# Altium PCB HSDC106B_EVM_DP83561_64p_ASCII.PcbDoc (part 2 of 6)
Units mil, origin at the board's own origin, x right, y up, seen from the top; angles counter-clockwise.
Board outline 8750.24 x 6394.7 mil, 6 copper layers (Top Layer, GND, SIG1, SIG2, GND1, Bottom Layer), stack 60.4 mil thick; 475 components, 330 nets, 1628 pads, 1086 vias.
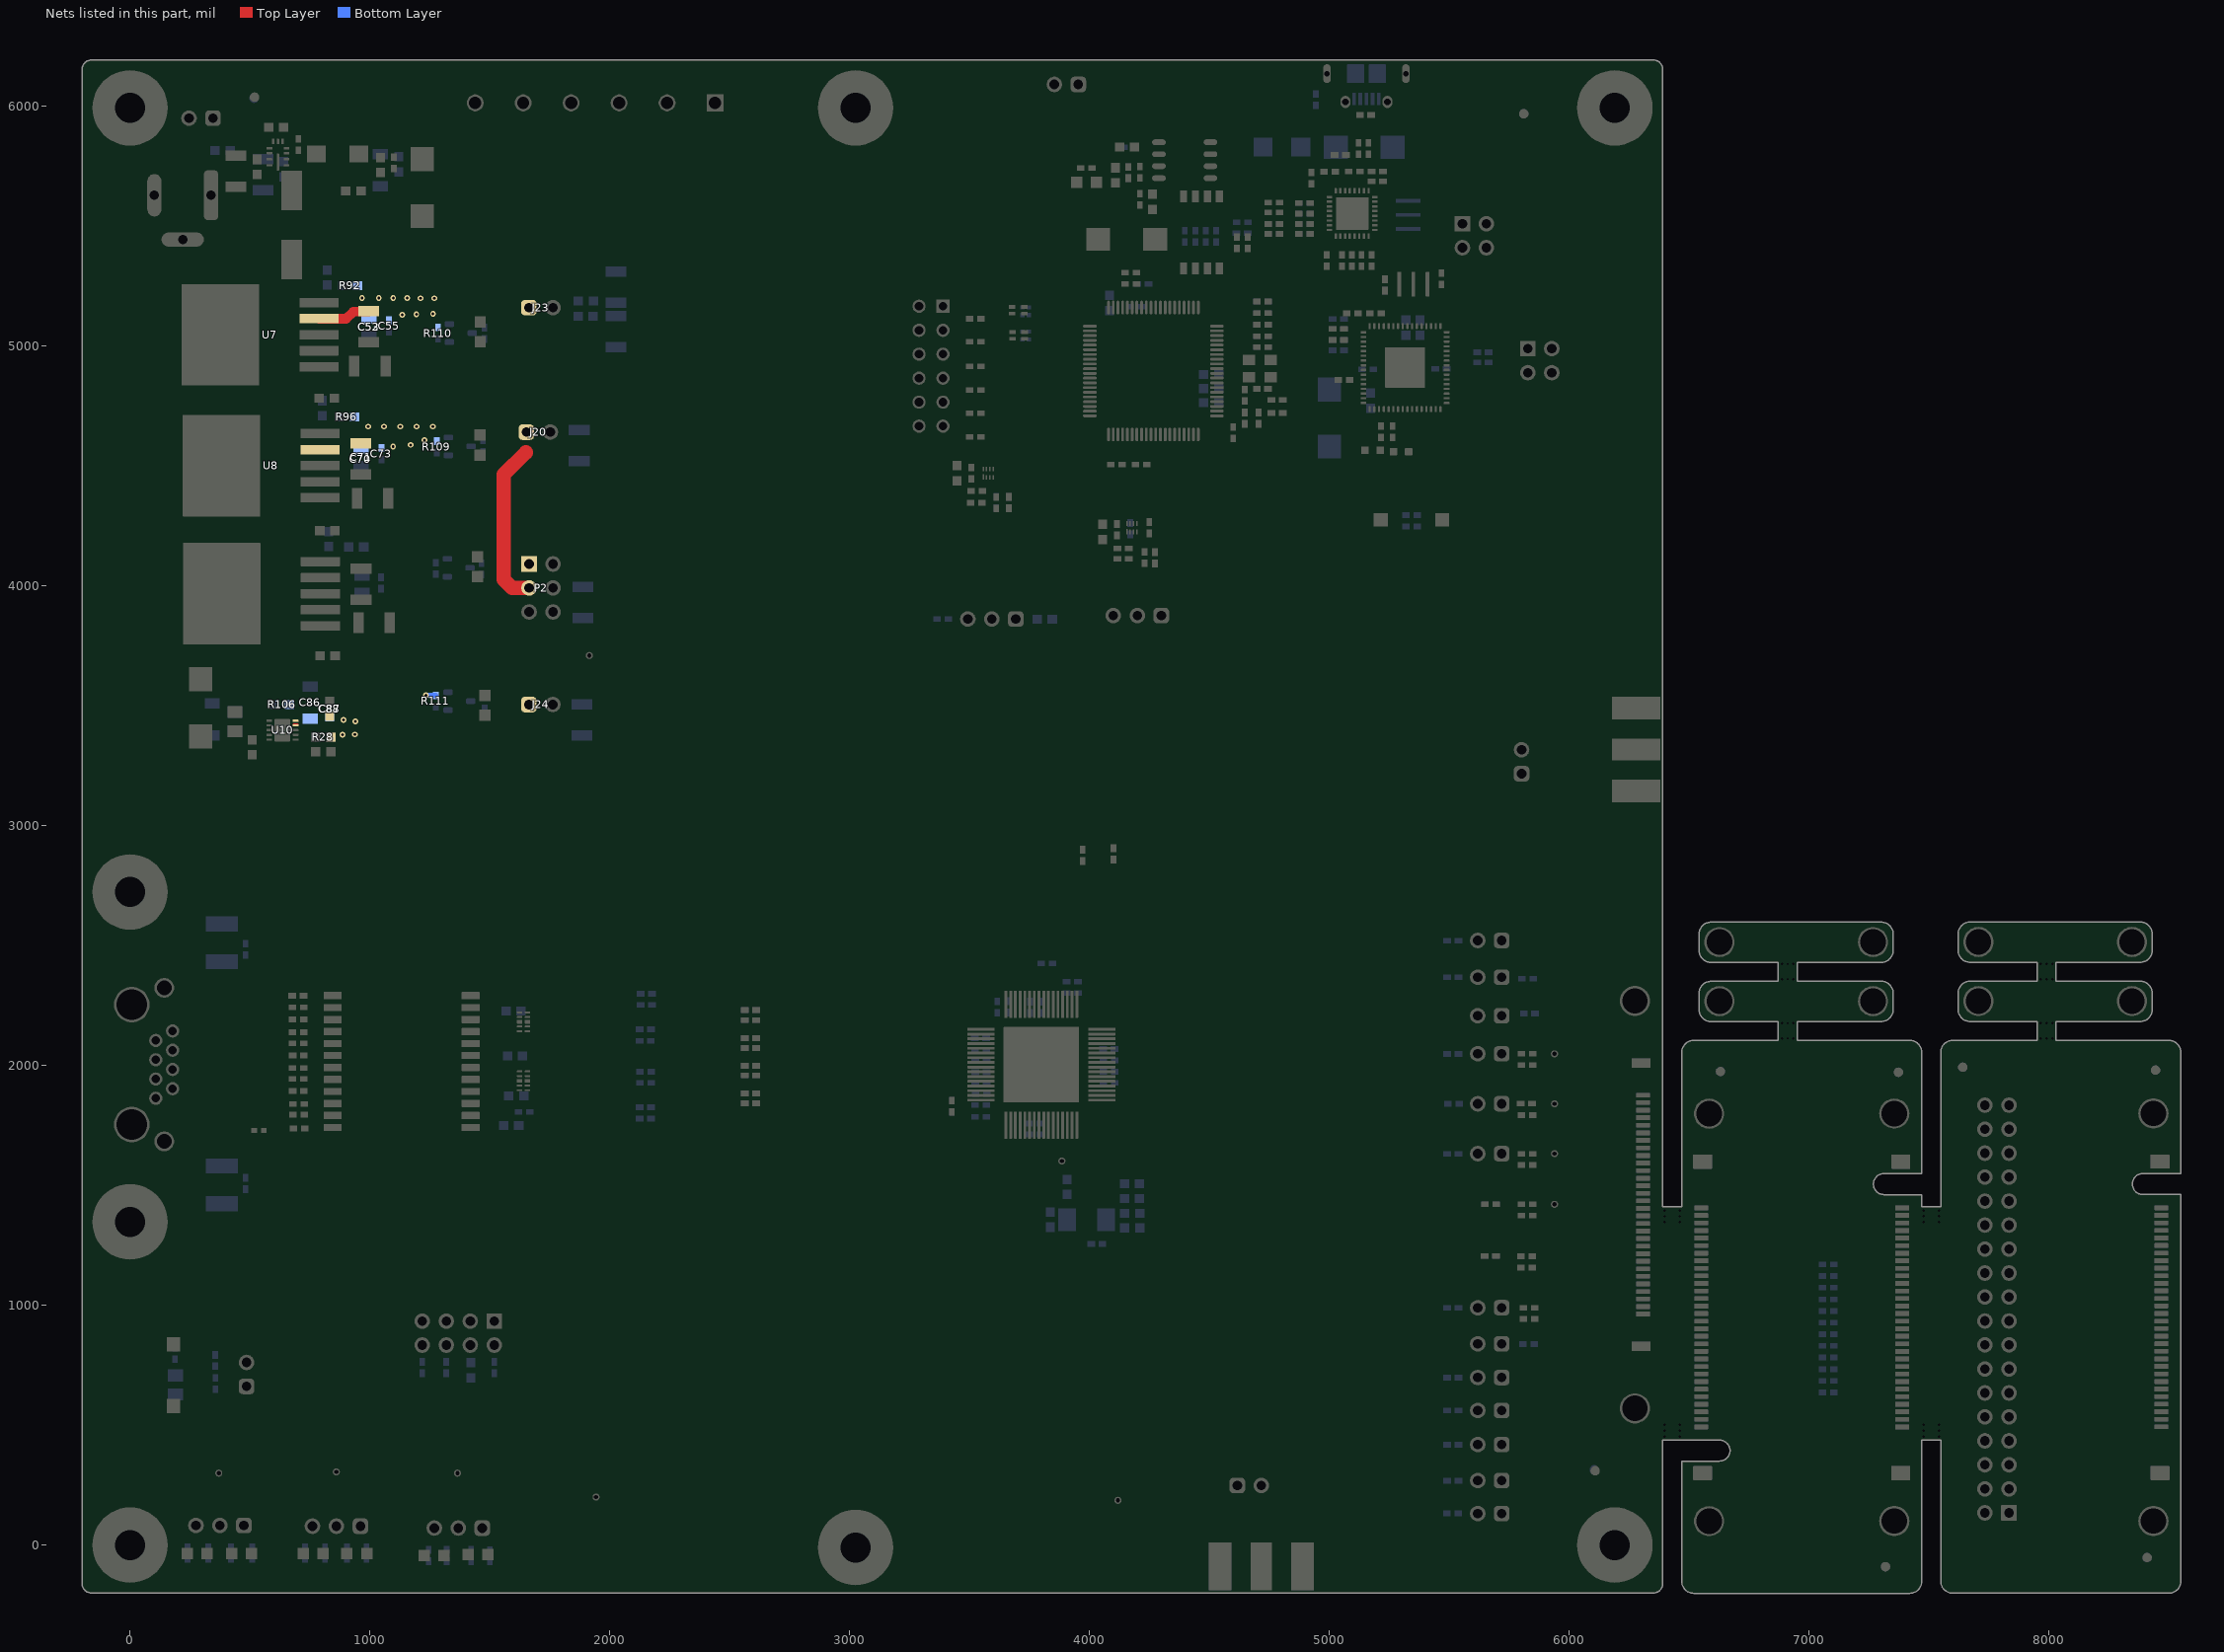
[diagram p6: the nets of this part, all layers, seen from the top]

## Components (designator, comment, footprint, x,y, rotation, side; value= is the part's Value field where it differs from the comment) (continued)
H4 "1902C" Keystone_1902C 0,5993.7 r180 bottom
H5 "1902C" Keystone_1902C 3025,5993.7 r180 bottom
H6 "1902C" Keystone_1902C 0,2723.83 r180 bottom
H7 "1902C" Keystone_1902C 6190.55,5993.7 r180 bottom
H8 "1902C" Keystone_1902C 6190.55,0 r180 bottom
J1 "ERF8-030-01-L-D-EM2-TR" Samtec_ERF8-030-01-x-D-EM2 8550.21,950 r270 top locked
J2 "TSW-118-07-G-D" TSW-118-07-G-D 7783.6,984.61 r90 top
J3 "TSW-102-07-G-D" TSW-102-07-G-D 5605,5460.7 r270 top
J4 "ERM8-030-01-L-D-EM2-TR" Samtec_ERM8-030-01-L-D-EM2 6390.55,1420 r180 top
J5 "TSW-102-07-G-S" TSW-102-07-G-S 5668.99,839.65 r180 top
J6 "TSW-102-07-G-S" TSW-102-07-G-S 5668.6,2207.61 r180 top
J8 "802-10-012-10-001000" Mill-Max_802-10-012-10-001000 3339.6,4916.61 r270 top
J9 "TSW-102-07-G-D" TSW-102-07-G-D 5877.6,4939.61 r270 top
J10 "TSW-102-07-G-S" TSW-102-07-G-S 485.95,711.76 r90 top
J11 "142-0701-851" Emerson_142-0701-851 4716.6,-199.39 r180 top
J12 "TSW-102-07-G-S" TSW-102-07-G-S 4666.6,248.61 r0 top
J13 "142-0701-851" Emerson_142-0701-851 6389.6,3318.11 r270 top
J14 "TSW-102-07-G-S" TSW-102-07-G-S 5801.67,3266.74 r90 top
J15 "CMP-0075407-2" TSW-103-07-G-S 3592.83,3862 r180 top
J16 "PJ-002AH" CUI_PJ-002AH 219.6,5629.61 r180 top
J17 "1729160" Phoenix_1729160 1939,6014.7 r180 top
J18 "TSW-102-07-G-S" TSW-102-07-G-S 295.6,5950.61 r180 top
J19 "ERF8-030-01-L-D-EM2-TR" Samtec_ERF8-030-01-x-D-EM2 7469.7,949.61 r270 top locked
J20 "TSW-102-07-G-S" TSW-102-07-G-S 1702,4641.61 r0 top
J21 "CMP-0075405-2" TSW-102-07-G-S 3903.6,6091.61 r180 top
J22 "ERF8-030-01-L-D-EM2-TR" Samtec_ERF8-030-01-x-D-EM2 6469.58,949.61 r90 top locked
J23 "CMP-0075405-2" TSW-102-07-G-S 1713,5160.7 r0 top
J24 "CMP-0075405-2" TSW-102-07-G-S 1712.6,3505.61 r0 top
J27 "1-406541-1" TEC_1-406541-1 114.53,2003.48 r270 top
J28 "CMP-0075407-2" TSW-103-07-G-S 1368.5,70.98 r180 top
J29 "CMP-0075405-2" TSW-102-07-G-S 5668.99,1632.34 r180 top locked
J30 "CMP-0075405-2" TSW-102-07-G-S 5668.99,1840.58 r180 top locked
J31 "CMP-0075405-2" TSW-102-07-G-S 5668.99,2048.82 r180 top
J32 "CMP-0075405-2" TSW-102-07-G-S 5668.99,990 r180 top locked
J33 "CMP-0075407-2" TSW-103-07-G-S 860.5,78.98 r180 top
J34 "CMP-0075405-2" TSW-102-07-G-S 5668.99,561.57 r180 top
J35 "CMP-0075405-2" TSW-102-07-G-S 5668.99,131.67 r180 top
J36 "CMP-0075405-2" TSW-102-07-G-S 5668.99,269.01 r180 top
J37 "CMP-0075405-2" TSW-102-07-G-S 5668.99,419.03 r180 top
J38 "CMP-0075407-2" TSW-103-07-G-S 374.5,81.98 r180 top
J39 "CMP-0075405-2" TSW-102-07-G-S 5668.99,698.77 r180 top
J40 "CMP-0075405-2" TSW-102-07-G-S 5668.99,2521.41 r180 top
J41 "CMP-0075405-2" TSW-102-07-G-S 5668.99,2368.28 r180 top
J42 "475890001" Molex_0475890001 5154.83,6193.7 r0 bottom
J43 "CMP-0075407-2" TSW-103-07-G-S 4199.6,3876.61 r180 top
L1 "SRP5030T-100M" SRP5030T 865.18,5801.61 r0 top
LD1 "CMP-0002917-2" QTLP630C_Green 1268,-44 r180 top
LD2 "CMP-0002917-2" QTLP630C_Green 1450,-40 r0 top
LD3 "CMP-0002917-2" QTLP630C_Green 763.89,-34.95 r180 top
LD4 "CMP-0002917-2" QTLP630C_Green 945.5,-35 r0 top
LD5 "CMP-0002917-2" QTLP630C_Green 280,-35 r180 top
LD6 "CMP-0002917-2" QTLP630C_Green 465,-35 r180 top
LD7 "QTLP630C4TR" QTLP630C_Green 3987.6,5682.7 r0 top
Logo1 "CE Mark" CE_Mark_5mm 587,1072 r0 top
Logo2 "Texas Instruments" TI_Stacked_Overlay_Small 5699,3956 r0 top
Logo3 "FCC disclaimer" FCC_disclaimer 12309,361.7 r90 top
Logo4 "WEEE logo" WEEE_Minimum 5913,4412 r0 top
M1 "NY PMS 440 0025 PH" "NY PMS 440 0025 PH" 6190.55,5993.7 r0 top locked
M2 "NY PMS 440 0025 PH" "NY PMS 440 0025 PH" 6190.55,0 r0 top locked
M3 "NY PMS 440 0025 PH" "NY PMS 440 0025 PH" 0,5993.7 r0 top locked
M4 "NY PMS 440 0025 PH" "NY PMS 440 0025 PH" 0,0 r0 top locked
M5 "NY PMS 440 0025 PH" "NY PMS 440 0025 PH" 3025,5993.7 r0 top locked
M6 "NY PMS 440 0025 PH" "NY PMS 440 0025 PH" 3025,-10 r0 top locked
M7 "NY PMS 440 0025 PH" "NY PMS 440 0025 PH" 0,2723.83 r0 top locked
M8 "NY PMS 440 0025 PH" "NY PMS 440 0025 PH" 0,1348.16 r0 top locked
P1 "CMP-0075408-3" TSW-104-07-G-D 1368.49,884.31 r180 top
P2 "TSW-103-07-G-D" TSW-103-07-G-D 1713.83,3991.7 r270 top
Q1 "DNBT8105-7" SOT-23 1370,4075.7 r0 bottom
Q2 "DNBT8105-7" SOT-23 1374.4,4582.1 r0 bottom
Q3 "DNBT8105-7" SOT-23 1379,5054.7 r0 bottom
Q4 "DNBT8105-7" SOT-23 1373,3519.7 r0 bottom
R1 "CRCW0402470RJNED" 0402#1 5216,4643.08 r90 top
R2 "CRCW0402470RJNED" 0402#1 5264,4643.08 r90 top
R3 "CRCW0402240KJNED" 0402#1 5037.6,5072.61 r180 top
R4 "CRCW0402220KJNED" 0402#1 5037.6,5025.7 r180 bottom
R5 "CRCW0402150KJNED" 0402#1 5037.6,5072.61 r0 bottom
R6 "CRCW0402220KJNED" 0402#1 5037.6,4982.7 r0 bottom
R7 "RC0402JR-070RL" 0402#1 5232.1,5255.55 r90 bottom
R8 "CRCW040247K0JNED" 0402#1 5096,5136.7 r180 top
R9 "RC0402JR-070RL" 0402#1 5640.6,4974.7 r0 bottom
R10 "RC0402JR-070RL" 0402#1 5640.6,4932.61 r0 bottom
R11 "ERJ-2GE0R00X" 0402#1 3971.39,2876.53 r90 top
R12 "ERJ-2GE0R00X" 0402#1 4100.51,2882.61 r90 top
R13 "ERJ-2GE0R00X" 0402#1 5830.98,838.61 r0 bottom
R14 "ERJ-2GE0R00X" 0402#1 5821.6,1841.61 r0 top
R15 "ERJ-2GE0R00X" 0402#1 5824.6,1631.61 r0 top
R16 "ERJ-2GE0R00X" 0402#1 5824.97,1421.22 r0 top
R17 "ERJ-2GE0R00X" 0402#1 5822.6,1204.24 r0 top
R18 "ERJ-2GE0R00X" 0402#1 5832.24,990 r0 top
R19 "ERJ-2GE0R00X" 0402#1 5824.97,2048.82 r0 top
R20 "ERJ-2GE0R00X" 0402#1 5832.24,942.76 r0 top
R21 "CMP-0025885-5" 0603 819.6,4783.61 r0 top
R22 "CMP-0025885-5" 0603 822.6,4230.61 r0 top
R23 "ERJ-2GE0R00X" 0402#1 5824.97,1793.33 r0 top
R24 "CMP-0025885-5" 0603 823.6,3708.61 r0 top
R25 "ERJ-2GE0R00X" 0402#1 5824.97,1585.09 r0 top
R26 "CMP-0025885-5" 0603 508.6,3327.1 r90 top
R27 "ERJ-2GE0R00X" 0402#1 5824.97,1373.98 r0 top
R28 "RC0603FR-071K87L" 0603 805.6,3370.15 r0 top
R29 "ERJ-2GE0R00X" 0402#1 5822.6,1157 r0 top
R30 "CRCW06034K99FKEAC" 0603 805.6,3370.15 r180 bottom
R31 "ERJ-2GE0R00X" 0402#1 5824.97,2001.57 r0 top
R32 "ERJ-2GE0R00X" 0402#1 5834.22,2216.48 r0 bottom
R33 "ERJ-2GE0R00X" 0402#1 5826.6,2361.61 r0 bottom
R34 "ERJ-2GE0R00X" 0402#1 3822,2426.17 r0 bottom
R35 "CRCW0402374KFKED" 0402#1 3530.65,4396.32 r0 top
R36 "ERJ-2RKF1004X" 0402#1 3527.6,4346.61 r180 top
R37 "CRCW0402374KFKED" 0402#1 4140.6,4156.61 r0 top
R38 "ERJ-2RKF1004X" 0402#1 4140.6,4113.61 r180 top
R39 "ERJ-2GE0R00X" 0402#1 3524.6,5114.61 r0 top
R40 "CRCW0603200KJNEA" 0603 3448.6,4470.61 r270 top
R41 "CRCW0603200KJNEA" 0603 4055.6,4225.61 r270 top
R42 "ERJ-2GE0R00X" 0402#1 3524.6,5018.61 r0 top
R43 "ERJ-2GE0R00X" 0402#1 3524.6,4915.61 r0 top
R44 "ERJ-2GE0R00X" 0402#1 3524.6,4816.61 r0 top
R45 "ERJ-2GE0R00X" 0402#1 3524.6,4720.61 r0 top
R46 "ERJ-2GE0R00X" 0402#1 3524.6,4621.61 r0 top
R47 "CRCW04022K20FKED" 0402#1 3611.45,4346.8 r270 top
R48 "CRCW04022K20FKED" 0402#1 4230.1,4118.11 r270 top
R49 "CRCW040210K0JNED" 0402#1 4721.6,5041.8 r0 top
R50 "CRCW040210K0JNED" 0402#1 4721.6,5090.07 r0 top
R51 "CRCW04022K20FKED" 0402#1 3663.64,4347.8 r270 top
R52 "CRCW040210K0JNED" 0402#1 4721.6,5138.34 r0 top
R53 "CRCW040210K0JNED" 0402#1 4721.6,5186.61 r0 top
R54 "ERJ-2GE0R00X" 0402#1 4169.71,4238.67 r90 bottom
R55 "ERJ-2GE0R00X" 0402#1 3611.45,4348.76 r90 bottom
R56 "ERJ-2GE0R00X" 0402#1 4249.6,4242.98 r90 top
R57 "ERJ-2GE0R00X" 0402#1 3663.64,4347.8 r90 bottom
R58 "CRCW040210K0JNED" 0402#1 4721.6,5041.8 r180 bottom
R59 "CRCW040210K0JNED" 0402#1 4721.6,5090.07 r180 bottom
R60 "CRCW040210K0JNED" 0402#1 4721.6,5138.34 r180 bottom
R61 "CRCW040210K0JNED" 0402#1 4721.6,5186.61 r180 bottom
R62 "CRCW04022K20FKED" 0402#1 4397.6,5458.61 r90 bottom
R63 "CRCW04022K20FKED" 0402#1 4441.6,5458.61 r90 bottom
R64 "CRCW04022K20FKED" 0402#1 4484.6,5458.61 r90 bottom
R65 "CRCW04022K20FKED" 0402#1 4528.6,5458.61 r90 bottom
R66 "CRCW04022K20FKED" 0402#1 4112.22,4506.61 r180 top
R67 "CRCW04022K20FKED" 0402#1 4214.98,4506.61 r0 top
R68 "CRCW04020000Z0ED" 0402#1 4721.6,4995.61 r180 top
R69 "RC0201JR-07470RL" 0201 3734.05,5161.57 r0 bottom
R70 "RC0201JR-07470RL" 0201 3734.05,5129.86 r0 bottom
R71 "RC0201JR-07470RL" 0201 3734.1,5060.61 r0 bottom
R72 "RC0201JR-07470RL" 0201 3734.1,5027.14 r0 bottom
R73 "CRCW04021K40FKED" 0402#1 4648,4699.7 r90 top
R74 "CRCW04021M00FKED" 0402#1 4599.6,4639.61 r270 top
R75 "CRCW040247K0JNED" 0402#1 5343,4295.61 r180 bottom
R76 "CRCW04020000Z0ED" 0402#1 4192.85,5164.73 r0 bottom
R77 "CMP-0025885-5" 0603 3906.6,1493.61 r90 bottom
R78 "CMP-0025885-5" 0603 4178.47,1383.8 r180 bottom
R79 "CRCW0402470RJNED" 0402#1 355.45,674.23 r90 bottom
R80 "ERJ-2GEJ101X" 0402#1 187.29,798.8 r90 bottom
R81 "CMP-0026727-1" 0402#1 4030.97,1255.8 r0 bottom
R82 "CMP-0025885-5" 0603 4177.6,1444.98 r180 bottom
R83 "RMCF0402FT10K0" 0402#1 3426.41,1829.61 r270 bottom
R84 "CMP-0025885-5" 0603 4177.6,1506.61 r180 bottom
R85 "CMP-0026890-5" 0402#1 4273.1,4117.61 r90 top
R86 "CMP-0026890-5" 0402#1 1518.49,740.69 r90 bottom
R87 "CMP-0026890-5" 0402#1 3388.6,3862 r180 bottom
R88 "CMP-0026890-5" 0402#1 1318.49,740.69 r90 bottom
R89 "CMP-0026890-5" 0402#1 1218.49,740.69 r90 bottom
R90 "CMP-0023246-5" 0603 3813.6,3861.61 r180 bottom
R91 "CMP-0022558-4" 0603 1420.6,729.61 r90 bottom
R92 "RC0603FR-071K2L" 0603 918,5252.7 r0 bottom
R93 "CRCW0603100KFKEA" 0603 931.6,5646.61 r0 top
R94 "CMP-0023374-3" 0603 822,5286.2 r270 bottom
R95 "CRCW060324K9FKEA" 0603 931.6,5646.61 r180 bottom
R96 "RC0603FR-072K55L" 0603 904,4705.7 r0 bottom
R97 "CMP-0025885-5" 0603 1899.6,5124.61 r0 bottom
R98 "CMP-0023374-3" 0603 801,4741.2 r270 bottom
R99 "CMP-0025885-5" 0603 1900,5188.7 r0 bottom
R100 "CMP-0022451-4" 0603 943,4162.7 r0 bottom
R101 "CMP-0023374-3" 0603 829,4195.7 r270 bottom
R102 "CMP-0026934-3" 0402#1 1465.6,4071.61 r90 bottom
R103 "CMP-0026934-3" 0402#1 1471.6,4583.61 r90 bottom
R104 "CMP-0026934-3" 0402#1 1477.6,5053.61 r90 bottom
R105 "CMP-0026934-3" 0402#1 1478.6,3513.61 r90 bottom
R106 "CMP-0022746-5" 0603 634,3505.7 r180 bottom
R107 "CMP-0026544-2" 0402#1 704.6,1737.61 r0 top
R108 "CRCW04022K49FKED" 0402#1 1274.6,4072.61 r270 bottom
R109 "CRCW04022K49FKED" 0402#1 1278.6,4580.61 r270 bottom
R110 "CRCW04022K49FKED" 0402#1 1283.6,5054.61 r270 bottom
R111 "CRCW04022K49FKED" 0402#1 1274.6,3519.61 r270 bottom
R112 "ERJ-2GE0R00X" 0402#1 703,1795 r0 top
R113 "ERJ-2GE0R00X" 0402#1 703,1839 r0 top
R114 "CMP-0026544-2" 0402#1 701.38,1893.61 r0 top
R115 "ERJ-2GE0R00X" 0402#1 701,1944 r0 top
R116 "ERJ-2GE0R00X" 0402#1 701,1990 r0 top
R117 "CMP-0026544-2" 0402#1 701.38,2041.7 r0 top
R118 "ERJ-2GE0R00X" 0402#1 701,2092 r0 top
R119 "ERJ-2GE0R00X" 0402#1 2586.65,2231.7 r0 top
R120 "ERJ-2GE0R00X" 0402#1 2586.65,2231.7 r0 bottom
R121 "ERJ-2GE0R00X" 0402#1 700.81,2138.61 r0 top
R122 "ERJ-2GE0R00X" 0402#1 2586.65,2189.7 r0 top
R123 "CMP-0026544-2" 0402#1 700,2192.09 r0 top
R124 "ERJ-2GE0R00X" 0402#1 2586.65,2189.7 r0 bottom
R125 "ERJ-2GE0R00X" 0402#1 700,2243 r0 top
R126 "ERJ-2GE0R00X" 0402#1 1643,1806 r180 bottom
R127 "ERJ-2GE0R00X" 0402#1 2586.65,2114.51 r0 top
R128 "ERJ-2GE0R00X" 0402#1 699.6,2290.61 r0 top
R129 "ERJ-2GE0R00X" 0402#1 2586.65,2114.51 r0 bottom
R130 "ERJ-2GE0R00X" 0402#1 7080.6,636.61 r0 bottom
R131 "ERJ-2GE0R00X" 0402#1 2586.65,2072.7 r0 top
R132 "ERJ-2GE0R00X" 0402#1 7080.6,685.15 r0 bottom
R133 "ERJ-2GE0R00X" 0402#1 2586.65,2072.7 r0 bottom
R134 "ERJ-2GE0R00X" 0402#1 7080.6,733.7 r0 bottom
R135 "ERJ-2GE0R00X" 0402#1 7080.6,782.24 r0 bottom
R136 "ERJ-2GE0R00X" 0402#1 7080.6,830.79 r0 bottom
R137 "ERJ-2GE0R00X" 0402#1 2586.65,1998.51 r0 top
R138 "ERJ-2GE0R00X" 0402#1 2586.65,1998.51 r0 bottom
R139 "ERJ-2GE0R00X" 0402#1 2586.65,1958.51 r0 top
R140 "ERJ-2GE0R00X" 0402#1 2586.65,1958.51 r0 bottom
R141 "ERJ-2GE0R00X" 0402#1 2586.65,1883.51 r0 top
R142 "ERJ-2GE0R00X" 0402#1 2586.65,1883.51 r0 bottom
R143 "ERJ-2GE0R00X" 0402#1 2586.65,1842.51 r0 top
R144 "ERJ-2GE0R00X" 0402#1 2586.65,1842.51 r0 bottom
R145 "CMP-0026727-1" 0402#1 482,1508 r270 bottom
R146 "CMP-0026727-1" 0402#1 482,2484 r90 bottom
R147 "CRCW0402470RJNED" 0402#1 1320.5,-43.4 r90 bottom
R148 "CRCW04022K49FKED" 0402#1 1244.5,-43.4 r270 bottom
R149 "CRCW0402470RJNED" 0402#1 1421.5,-43.4 r90 bottom
R150 "CRCW04022K49FKED" 0402#1 1500,-45 r90 bottom
R151 "CRCW04022K49FKED" 0402#1 5514.94,1631.93 r180 bottom
R152 "CRCW04026K04FKED" 0402#1 5671.47,1205.42 r180 top
R153 "CRCW04022K49FKED" 0402#1 5518.64,1840.17 r180 bottom
R154 "CRCW04022K49FKED" 0402#1 5671.47,1205.42 r0 bottom
R155 "CRCW04026K04FKED" 0402#1 5672.01,1421.22 r180 top
R156 "CRCW04022K49FKED" 0402#1 5514.94,2048.41 r180 bottom
R157 "CRCW0402470RJNED" 0402#1 812.5,-33.4 r90 bottom
R158 "CRCW04022K49FKED" 0402#1 5672.01,1421.22 r0 bottom
R159 "CRCW04022K49FKED" 0402#1 729.5,-33.4 r270 bottom
R160 "CRCW04022K49FKED" 0402#1 5514.94,989.59 r180 bottom
R161 "CRCW0402470RJNED" 0402#1 904,-33.4 r90 bottom
R162 "CRCW04022K49FKED" 0402#1 986,-33.4 r90 bottom
R163 "CRCW04022K49FKED" 0402#1 5514.94,561.16 r180 bottom
R164 "CRCW04022K49FKED" 0402#1 5513.6,132.61 r180 bottom
R165 "CRCW04022K49FKED" 0402#1 5514.94,268.61 r180 bottom
R166 "CRCW0402470RJNED" 0402#1 326.49,-33.43 r90 bottom
R167 "CRCW04022K49FKED" 0402#1 5514.94,418.62 r180 bottom
R168 "CRCW04022K49FKED" 0402#1 239.5,-33.4 r270 bottom
R169 "CRCW04022K49FKED" 0402#1 5514.94,698.36 r180 bottom
R170 "CRCW0402470RJNED" 0402#1 509.5,-33.4 r90 bottom
R171 "CRCW04022K49FKED" 0402#1 420.5,-33.4 r90 bottom
R172 "CRCW04022K49FKED" 0402#1 5514.94,2521 r180 bottom
R173 "CRCW04022K49FKED" 0402#1 5514.94,2367.87 r180 bottom
R174 "CRCW0402100KDHEDP" 0402#1 4210,5725.04 r90 top
R175 "CRCW0402470RJNED" 0402#1 3987.6,5742.61 r0 top
R176 "CRCW0402165KFKED" 0402#1 4210,5612.94 r90 top
R177 "CRCW040233R0JNED" 0402#1 4944,6027.7 r270 bottom
R178 "CRCW04021K50FKED" 0402#1 5200,5729 r0 top
R179 "CRCW040210K0JNED" 0402#1 4989,5357.7 r270 top
R180 "CRCW040227R0JNED" 0402#1 4648,4795.7 r90 top
R181 "CRCW040222R0JNED" 0402#1 5122,5825 r270 top
R182 "CRCW040222R0JNED" 0402#1 5163.41,5824.5 r270 top
R183 "CRCW040227R0JNED" 0402#1 4705,4699.7 r270 top
R184 "CRCW040222R0JNED" 0402#1 4895.98,5596.61 r0 top
R185 "CRCW040222R0JNED" 0402#1 4896.6,5552.61 r0 top
R186 "CRCW040215K0FKED" 0402#1 4769,5557.5 r0 top
R187 "CRCW040215K0FKED" 0402#1 4769,5598.72 r0 top
R188 "CRCW040215K0FKED" 0402#1 5053.44,5357.32 r90 top
R189 "CRCW040215K0FKED" 0402#1 5094.25,5357.61 r90 top
R190 "CRCW040215K0FKED" 0402#1 5134.6,5357.61 r90 top
R191 "CRCW040215K0FKED" 0402#1 5176.79,5357.61 r90 top
R192 "CRCW040222R0JNED" 0402#1 4896.41,5509.5 r0 top
R193 "CRCW040222R0JNED" 0402#1 4896.41,5468.5 r0 top
R194 "CRCW040215K0FKED" 0402#1 4769,5468.5 r0 bottom
R195 "CRCW040215K0FKED" 0402#1 4769,5509.5 r0 bottom
R196 "CRCW040227R0JNED" 0402#1 4769,5509.5 r0 top
R197 "CRCW04021K40FKED" 0402#1 4614.59,5430.77 r270 top
R198 "CRCW040247K0JNED" 0402#1 5045.62,5797.7 r180 top
R199 "CRCW040227R0JNED" 0402#1 4769,5468.5 r0 top
R200 "CRCW04021M00FKED" 0402#1 4659.87,5430.77 r90 top
R201 "ERJ-2GE0R00X" 0402#1 7080.6,879.33 r0 bottom
R202 "ERJ-2GE0R00X" 0402#1 7080.6,976.42 r0 bottom
R203 "ERJ-2GE0R00X" 0402#1 7080.6,1170.61 r0 bottom
R204 "ERJ-2GE0R00X" 0402#1 7080.6,1122.06 r0 bottom
R205 "ERJ-2GE0R00X" 0402#1 7080.6,1073.51 r0 bottom
R206 "ERJ-2GE0R00X" 0402#1 7080.6,1024.97 r0 bottom
R207 "ERJ-2GE0R00X" 0402#1 7080.6,927.88 r0 bottom
S1 "218-4LPST" SW_218-4LPST 4467,5474.7 r90 top
S2 "KSR221GLFS" KSR 5343,4275.7 r180 top
S3 "KSR221GLFS" KSR 181.41,708.61 r90 top
SH-J1 "M7582-05" Harwin_M7582-05 5671.6,2046 r180 top
SH-J2 "M7582-05" Harwin_M7582-05 324,69 r180 top
SH-J3 "M7582-05" Harwin_M7582-05 793.46,75 r180 top
SH-J4 "M7582-05" Harwin_M7582-05 1286.41,98 r180 top
SH-J5 "M7582-05" Harwin_M7582-05 1703,3507 r180 top
SH-J6 "M7582-05" Harwin_M7582-05 1686,4085 r180 top
SH-J7 "M7582-05" Harwin_M7582-05 1695,4636.75 r180 top
SH-J8 "M7582-05" Harwin_M7582-05 1710.75,5165.89 r180 top
T1 "1000B-5001X" FP-1000B-5001X_SMD24-MFG 1132.26,2016.7 r90 top
TP1 "TP_H0.45P0.75" TP_H045P075 1365,300 r0 top
TP2 "TP_H0.45P0.75" TP_H045P075 370,300 r0 top
TP3 "TP_H0.45P0.75" TP_H045P075 860,305 r0 top
TP4 "TP_H0.45P0.75" TP_H045P075 1943,200.61 r0 top
TP5 "TP_H0.45P0.75" TP_H045P075 1915,3710 r0 top
TP6 "TP_H0.45P0.75" TP_H045P075 4118.6,186.61 r0 top
TP7 "TP_H0.45P0.75" TP_H045P075 5938.99,1840.58 r0 top
TP8 "TP_H0.45P0.75" TP_H045P075 5938.99,2048.82 r270 top locked
TP9 "TP_H0.45P0.75" TP_H045P075 5938.99,1632.34 r270 top locked
TP10 "TP_H0.45P0.75" TP_H045P075 5938.99,1421.22 r270 top locked
U1 "MSP430F5528IRGCR" RGC0064B 5315.99,4910.69 r0 top locked
U2 "LSF0102DQER" DQE0008A 3577.93,4470.51 r90 top
U3 "LSF0102DQER" DQE0008A 4176.6,4242.61 r90 top
U4 "MSP430F5529IPN" PN0080A_N 4266.47,4896.46 r270 top locked
U5 "DP83561HBE/EM" HBE0064B-MFG 3799.56,2003.23 r0 top locked
U6 "LMR33620ARNXT" RNX0012B 616.6,5798.61 r180 top
U7 "TL1963AQKTTRQ1" KTT0005A_N 542.35,5047.7 r180 top
U8 "TL1963AQKTTRQ1" KTT0005A_N 546.35,4501.7 r180 top
U9 "TL1963AQKTTRQ1" KTT0005A_N 547.35,3967.7 r180 top
U10 "TPS74701DRCR" DRC0010J 635,3398.7 r0 top locked
U11 "CMP-0073613-2" DQA0010A 1640.56,1936.31 r0 top
U12 "CMP-0073613-2" DQA0010A 1640.56,2182.31 r0 top
U13 "TL5209DR" D0008A_N 4397,5775.7 r0 top
U14 "TUSB2046BIRHBT" RHB0032E 5095.41,5553.5 r270 top
VPP_TP1 "TP_H0.45P0.75" TP_H045P075 3885,1602.05 r90 top
XTAL1 "CMP-0004614-3" XTAL_ABM3 3987.97,1356.8 r180 bottom
Y1 "CSTNR4M00GH5L000R0" MuRata_CSTNR 5350.6,5258.61 r0 top
Y2 "ECS-240-20-33-DU-TR" ECS_ECX-32 4710.6,4906.61 r270 top
Y3 "CSTCR6M00G53Z-R0" Murata_CSTCR_G 5329.46,5547.35 r270 bottom
ZZ1 "These assemblies are ESD sensitive, ESD precautions shall be observed." AssemblyNote 3959.7,-1368 r0 top
ZZ2 "These assemblies must be clean and free from flux and all contaminants. Use of no clean flux is not acceptable." AssemblyNote 2406.7,-1191 r0 top
ZZ3 "These assemblies must comply with workmanship standards IPC-A-610 Class 2, unless otherwise specified." AssemblyNote 2733.7,-1014 r0 top

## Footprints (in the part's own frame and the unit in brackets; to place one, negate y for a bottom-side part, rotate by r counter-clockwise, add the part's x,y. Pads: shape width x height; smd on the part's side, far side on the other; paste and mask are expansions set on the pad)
0201 [mm] "Data from Kemet datasheet CC101_COM dated 7/28/11"
  rect 0.46x0.42 smd mask+0: 1(-0.33,0) 2(0.33,0)
0402#1 [mm] "0402 from SM-752 data"
  rect 0.8x0.6 smd: 1(-0.6,0) 2(0.6,0)
  silkscreen extent -1.22,-0.52 1.22,0.52
0402#2 [mm] "Chip Capacitor, Body 1.0x0.5mm, IPC High Density"
  rect 0.6x0.5 smd: 1(-0.5,0) 2(0.5,0)
0603 [mm] "0603 from SM-752 data"
  rect 1x0.95 smd: 1(-0.8,0) 2(0.8,0)
  silkscreen extent -1.52,-0.69 1.52,0.69
0805_HV [mil] "0805 with 30mil clearance between pads"
  rect 50x63 smd: 1(-40,0) 2(40,0)
  silkscreen extent -74,-40 74,40
1206_190 [mm] "1206_190"
  rect 1.1x1.6 smd: 1(-1.7,0) 2(1.7,0)
  silkscreen extent -0.9,-1 0.9,1
1210_280 [mm] "SMD, 2-Leads, Body 3.6x2.8mm, Height 2.8mm"
  rect 1.1x2.2 smd: 1(-1.65,0) 2(1.65,0)
  silkscreen extent -0.84,-1.4 0.84,1.4
1812_254 [mm] "SMD, 2-Leads, Body 4.8x3.4mm"
  rect 1.6x3.4 smd: 1(-2,0) 2(2,0)
  silkscreen extent -0.8,-1.7 0.8,1.7
7343-31 [mm] "Medium Density based on Kemet T495 dimensions"
  rect 2.55x2.45 smd: 1(-3.025,0) 2(3.025,0)
  silkscreen extent -4.56,-2.3 3.8,2.3
AssemblyNote [mil] "Assembly Note"
CAPSMT_62_HA0 [mm] "8 x 10mm:  Chemi-Con HA0"
  rect 4.2x2.2 smd: 1(-3.65,0) 2(3.65,0)
  silkscreen extent -4.25,-4.25 4.25,4.25
CE_Mark_5mm [mil] "Minimum text height for CE Mark"
CUI_PJ-002AH [mm] "DC POWER JACK, R/A, TH"
  rrect50% 1.5x5.25 hole 1 square: 1(-3,0)
  oval 1.5x4.5 hole 1 square: 2(3,0)
  oval 4.5x1.5 hole 1 square: 3(0,4.7)
  silkscreen extent -4.1,-4.5 10.7,4.5
D0008A_N [mm] "SOIC, 8-Leads, Body 4.9x3.9mm, Pitch 1.27mm, IPC Medium Density"
  oval 1.45x0.6 smd: 1(-2.725,1.905) 2(-2.725,0.635) 3(-2.725,-0.635) 4(-2.725,-1.905) 5(2.725,-1.905) 6(2.725,-0.635) 7(2.725,0.635) 8(2.725,1.905)
  silkscreen extent -3.3,-2.5 0.9,2.5
DQA0010A [mm] "SON, 10-Leads, Body 1x2.5mm, Pitch 0.5mm, TI Recommended"
  rrect50% 0.565x0.2 smd: 1(-0.417,1) 2(-0.417,0.5) 4(-0.417,-0.5) 5(-0.417,-1) 6(0.417,-1) 7(0.417,-0.5) 9(0.417,0.5) 10(0.417,1)
  rrect28% 0.565x0.36 on Top Paste: 3(-0.417,0) 8(0.417,0)
  rrect25% 0.565x0.4 smd paste-0.2: 3(-0.417,0) 8(0.417,0)
  silkscreen extent -0.67,-1.45 0.55,1.45
DQE0008A [mm] "SON, 8-Leads, Body 1.4x1mm, Pitch 0.35mm, TI Recommended"
  rect 0.6x0.16 smd: 1(-0.4,0.525)
  rect 0.5x0.16 smd: 2(-0.45,0.175) 3(-0.45,-0.175) 4(-0.45,-0.525) 5(0.45,-0.525) 6(0.45,-0.175) 7(0.45,0.175) 8(0.45,0.525)
  silkscreen extent -0.7,-0.85 0.4,0.85
DRC0010J [mm] "VSON-10"
  rrect42% 0.6x0.24 smd: 1(-1.4,1) 2(-1.4,0.5) 3(-1.4,0) 4(-1.4,-0.5) 5(-1.4,-1) 6(1.4,-1) 7(1.4,-0.5) 8(1.4,0) 9(1.4,0.5) 10(1.4,1)
  rrect12% 1.65x2.4 smd paste-1 mask+0: 11(0,0)
ECS_ECX-32 [mm] "SMD, 4-Leads, Body 3.2x2.5mm"
  rect 1.1x1.3 smd: 1(-0.9,1.15) 2(-0.9,-1.15) 3(0.9,-1.15) 4(0.9,1.15)
  silkscreen extent -1.31,-0.2 1.3,2.37
Emerson_142-0701-851 [mil] "Cinch Connectivity"
  rect 90x200 smd: 1(0,-110)
  rect 95x200 smd: 2(-172.5,-110) 3(172.5,-110)
  rect 95x200 smd far side: 4(172.5,-110) 5(-172.5,-110)
  silkscreen extent -235,-220 235,0
FCC_disclaimer [mil]
Fiducial10-30 [mm]
  round 1 smd mask+0: 1(0,0)
  Top Layer keep-out circle w1.678: c0,0 r0.75
FP-1000B-5001X_SMD24-MFG [mm]
  rrect13% 0.76x1.905 smd paste+0 mask+0: 1(-6.985,-7.305) 2(-5.715,-7.305) 3(-4.445,-7.305) 4(-3.175,-7.305) 5(-1.905,-7.305) 6(-0.635,-7.305) 7(0.635,-7.305) 8(1.905,-7.305) 9(3.175,-7.305) 10(4.445,-7.305) 11(5.715,-7.305) 12(6.985,-7.305) 13(6.985,7.305) 14(5.715,7.305) 15(4.445,7.305) 16(3.175,7.305) 17(1.905,7.305) 18(0.635,7.305) 19(-0.635,7.305) 20(-1.905,7.305) 21(-3.175,7.305) 22(-4.445,7.305) 23(-5.715,7.305) 24(-6.985,7.305)
  silkscreen extent -8.89,-9.03 8.89,6.22
Harwin_M7582-05 [mil] "Single Operation 2.54mm Pitch Open Top Jumper Socket"
HBE0064B-MFG [mm]
  rrect33% 2.895x0.3 smd paste+0 mask+0: 1(-6.397,3.75) 2(-6.397,3.25) 3(-6.397,2.75) 4(-6.397,2.25) 5(-6.397,1.75) 6(-6.397,1.25) 7(-6.397,0.75) 8(-6.397,0.25) 9(-6.397,-0.25) 10(-6.397,-0.75) 11(-6.397,-1.25) 12(-6.397,-1.75) 13(-6.397,-2.25) 14(-6.397,-2.75) 15(-6.397,-3.25) 16(-6.397,-3.75) 33(6.397,-3.75) 34(6.397,-3.25) 35(6.397,-2.75) 36(6.397,-2.25) 37(6.397,-1.75) 38(6.397,-1.25) 39(6.397,-0.75) 40(6.397,-0.25) 41(6.397,0.25) 42(6.397,0.75) 43(6.397,1.25) 44(6.397,1.75) 45(6.397,2.25) 46(6.397,2.75) 47(6.397,3.25) 48(6.397,3.75)
  rrect33% 0.3x2.895 smd paste+0 mask+0: 17(-3.75,-6.397) 18(-3.25,-6.397) 19(-2.75,-6.397) 20(-2.25,-6.397) 21(-1.75,-6.397) 22(-1.25,-6.397) 23(-0.75,-6.397) 24(-0.25,-6.397) 25(0.25,-6.397) 26(0.75,-6.397) 27(1.25,-6.397) 28(1.75,-6.397) 29(2.25,-6.397) 30(2.75,-6.397) 31(3.25,-6.397) 32(3.75,-6.397) 49(3.75,6.397) 50(3.25,6.397) 51(2.75,6.397) 52(2.25,6.397) 53(1.75,6.397) 54(1.25,6.397) 55(0.75,6.397) 56(0.25,6.397) 57(-0.25,6.397) 58(-0.75,6.397) 59(-1.25,6.397) 60(-1.75,6.397) 61(-2.25,6.397) 62(-2.75,6.397) 63(-3.25,6.397) 64(-3.75,6.397)
  rrect1% 8x8 smd paste-1000 mask+0: 65(0,0)
  silkscreen extent -8.54,-5.52 5.52,5.52
HSMF-C165_RG [mm] "SMD, 4-Leads, Body 1.6x0.8mm"
  rect 0.7x0.4 smd: 1(-0.65,0.35) 2(-0.65,-0.35) 3(0.65,0.35) 4(0.65,-0.35)
  silkscreen extent -1,-0.8 1.5,0.8
Keystone_1902C [mil] "Hex Standoff, 4-40 threaded, nylon"
  round 1 on Mech4: 0(0,0)
KSR [mm] "C&K Components SPST switch"
  rect 1.5x1.4 smd: 1(-3.25,0) 2(3.25,0)
  silkscreen extent -3.2,-2 3.2,2
KTT0005A_N [mm] "D2-PAK, 6-Leads, Body 8.9x10.2mm, Pitch 1.7mm, Lead Span 15.2mm, IPC Medium Density"
  rrect10% 4.15x1 smd: 1(-6.25,3.4) 2(-6.25,1.7) 3(-6.25,0) 4(-6.25,-1.7) 5(-6.25,-3.4)
  rrect1% 8.2x10.75 smd: 6(4.2,0)
  silkscreen extent -6.43,-5.35 -0.3,5.35
Mill-Max_802-10-012-10-001000 [mm] "Header, 2.54 mm, 6x2, TH"
  rect 1.4x1.4 hole 0.9: 1(-6.35,1.27)
  round 1.4 hole 0.9: 2(-6.35,-1.27) 3(-3.81,1.27) 4(-3.81,-1.27) 5(-1.27,1.27) 6(-1.27,-1.27) 7(1.27,1.27) 8(1.27,-1.27) 9(3.81,1.27) 10(3.81,-1.27) 11(6.35,1.27) 12(6.35,-1.27)
  silkscreen extent -7.96,-2.54 7.62,2.54
Molex_0475890001 [mm] "Molex"
  rrect25% 0.4x1.35 smd: 1(-1.3,4.125) 2(-0.65,4.125) 3(0,4.125) 4(0.65,4.125) 5(1.3,4.125)
  oval 1.05x1.3 hole 0.7 slot 0.85 at 90 deg: 6(2.225,4.45) 11(-2.225,4.45)
  oval 0.8x2 hole 0.6 slot 1.3 at 90 deg: 7(4.175,1.45) 10(-4.175,1.45)
  rrect6% 1.8x2 smd: 8(1.15,1.45) 9(-1.15,1.45)
  silkscreen extent -3.75,2.85 3.75,4.3
Murata_CSTCR_G [mm] "Murata"
  rect 0.4x2.6 smd: 1(-1.5,0) 2(0,0) 3(1.5,0)
MuRata_CSTNR [mm] "SMD, 3-Leads, Body 4.5x2mm, Pitch 1.5mm"
  rrect25% 0.4x2.6 smd: 1(-1.5,0) 2(0,0) 3(1.5,0)
"NY PMS 440 0025 PH" [mm] "4-40 nylon screw and mounting hole"
  round 8 hole 3.2: 1(0,0)
Phoenix_1729160 [mm] "Phoenix Contact"
  rect 1.8x1.8 hole 1.3 paste+0: 1(-12.7,0)
  round 1.8 hole 1.3 paste+0: 2(-7.62,0) 3(-2.54,0) 4(2.54,0) 5(7.62,0) 6(12.7,0)
  silkscreen extent -15.81,-4.63 15.24,4.05
PN0080A_N [mm] "QFP, 80-Leads, Body 12x12mm, Pitch 0.5mm, IPC Medium Density"
  oval 1.45x0.3 smd: 1(-6.725,4.75) 2(-6.725,4.25) 3(-6.725,3.75) 4(-6.725,3.25) 5(-6.725,2.75) 6(-6.725,2.25) 7(-6.725,1.75) 8(-6.725,1.25) 9(-6.725,0.75) 10(-6.725,0.25) 11(-6.725,-0.25) 12(-6.725,-0.75) 13(-6.725,-1.25) 14(-6.725,-1.75) 15(-6.725,-2.25) 16(-6.725,-2.75) 17(-6.725,-3.25) 18(-6.725,-3.75) 19(-6.725,-4.25) 20(-6.725,-4.75) 41(6.725,-4.75) 42(6.725,-4.25) 43(6.725,-3.75) 44(6.725,-3.25) 45(6.725,-2.75) 46(6.725,-2.25) 47(6.725,-1.75) 48(6.725,-1.25) 49(6.725,-0.75) 50(6.725,-0.25) 51(6.725,0.25) 52(6.725,0.75) 53(6.725,1.25) 54(6.725,1.75) 55(6.725,2.25) 56(6.725,2.75) 57(6.725,3.25) 58(6.725,3.75) 59(6.725,4.25) 60(6.725,4.75)
  oval 0.3x1.45 smd: 21(-4.75,-6.725) 22(-4.25,-6.725) 23(-3.75,-6.725) 24(-3.25,-6.725) 25(-2.75,-6.725) 26(-2.25,-6.725) 27(-1.75,-6.725) 28(-1.25,-6.725) 29(-0.75,-6.725) 30(-0.25,-6.725) 31(0.25,-6.725) 32(0.75,-6.725) 33(1.25,-6.725) 34(1.75,-6.725) 35(2.25,-6.725) 36(2.75,-6.725) 37(3.25,-6.725) 38(3.75,-6.725) 39(4.25,-6.725) 40(4.75,-6.725) 61(4.75,6.725) 62(4.25,6.725) 63(3.75,6.725) 64(3.25,6.725) 65(2.75,6.725) 66(2.25,6.725) 67(1.75,6.725) 68(1.25,6.725) 69(0.75,6.725) 70(0.25,6.725) 71(-0.25,6.725) 72(-0.75,6.725) 73(-1.25,6.725) 74(-1.75,6.725) 75(-2.25,6.725) 76(-2.75,6.725) 77(-3.25,6.725) 78(-3.75,6.725) 79(-4.25,6.725) 80(-4.75,6.725)
  silkscreen extent -6.85,-5.6 5.6,5.6
QTLP630C_Green [mm] "SMT, 2-Leads, Body 2x1.25mm"
  rect 1.2x1.2 smd: 1(-1.05,0) 2(1.05,0)
  silkscreen extent -0.15,-0.8 2.15,0.8
RGC0064B [mm] "VQFN-64"
  rrect42% 0.6x0.24 smd mask+0: 1(-4.4,3.75) 2(-4.4,3.25) 3(-4.4,2.75) 4(-4.4,2.25) 5(-4.4,1.75) 6(-4.4,1.25) 7(-4.4,0.75) 8(-4.4,0.25) 9(-4.4,-0.25) 10(-4.4,-0.75) 11(-4.4,-1.25) 12(-4.4,-1.75) 13(-4.4,-2.25) 14(-4.4,-2.75) 15(-4.4,-3.25) 16(-4.4,-3.75) 33(4.4,-3.75) 34(4.4,-3.25) 35(4.4,-2.75) 36(4.4,-2.25) 37(4.4,-1.75) 38(4.4,-1.25) 39(4.4,-0.75) 40(4.4,-0.25) 41(4.4,0.25) 42(4.4,0.75) 43(4.4,1.25) 44(4.4,1.75) 45(4.4,2.25) 46(4.4,2.75) 47(4.4,3.25) 48(4.4,3.75)
  rrect42% 0.24x0.6 smd mask+0: 17(-3.75,-4.4) 18(-3.25,-4.4) 19(-2.75,-4.4) 20(-2.25,-4.4) 21(-1.75,-4.4) 22(-1.25,-4.4) 23(-0.75,-4.4) 24(-0.25,-4.4) 25(0.25,-4.4) 26(0.75,-4.4) 27(1.25,-4.4) 28(1.75,-4.4) 29(2.25,-4.4) 30(2.75,-4.4) 31(3.25,-4.4) 32(3.75,-4.4) 49(3.75,4.4) 50(3.25,4.4) 51(2.75,4.4) 52(2.25,4.4) 53(1.75,4.4) 54(1.25,4.4) 55(0.75,4.4) 56(0.25,4.4) 57(-0.25,4.4) 58(-0.75,4.4) 59(-1.25,4.4) 60(-1.75,4.4) 61(-2.25,4.4) 62(-2.75,4.4) 63(-3.25,4.4) 64(-3.75,4.4)
  rrect2% 4.25x4.25 smd paste-2.112: 65(0,0)
RHB0032E [mm] "QFN, 32-Leads, Body 5x5mm, Pitch 0.5mm, Thermal Pad 3.45x3.45mm, TI Recommended"
  rrect40% 0.6x0.25 smd: 1(-2.4,1.75) 2(-2.4,1.25) 3(-2.4,0.75) 4(-2.4,0.25) 5(-2.4,-0.25) 6(-2.4,-0.75) 7(-2.4,-1.25) 8(-2.4,-1.75) 17(2.4,-1.75) 18(2.4,-1.25) 19(2.4,-0.75) 20(2.4,-0.25) 21(2.4,0.25) 22(2.4,0.75) 23(2.4,1.25) 24(2.4,1.75)
  rrect40% 0.25x0.6 smd: 9(-1.75,-2.4) 10(-1.25,-2.4) 11(-0.75,-2.4) 12(-0.25,-2.4) 13(0.25,-2.4) 14(0.75,-2.4) 15(1.25,-2.4) 16(1.75,-2.4) 25(1.75,2.4) 26(1.25,2.4) 27(0.75,2.4) 28(0.25,2.4) 29(-0.25,2.4) 30(-0.75,2.4) 31(-1.25,2.4) 32(-1.75,2.4)
  rrect3% 3.45x3.45 smd paste-1.725: 33(0,0)
  rrect7% 1.49x1.49 on Top Paste: ""(-0.845,0.845) ""(-0.845,-0.845) ""(0.845,0.845) ""(0.845,-0.845)
  silkscreen extent -2.72,-2.73 2.72,2.73
RNX0012B [mm] "VQFN-HR-12"
  rrect40% 0.6x0.25 smd: 1(-0.9,1.125) 2(-0.9,0.475) 3(-0.9,-0.175) 4(-0.9,-0.675) 8(0.9,-0.675) 9(0.9,-0.175) 10(0.9,0.475) 11(0.9,1.125)
  rrect40% 0.25x0.6 smd: 5(-0.5,-1.4) 6(0,-1.4) 7(0.5,-1.4)
  rrect40% 0.25x1.825 smd paste-0.175: 12(0,0.788)
Samtec_ERF8-030-01-x-D-EM2 [mm] "Receptacle, 0.8mm, 30x2, Edge Mount"
  rrect20% 0.5x1.48 smd paste-1: 1(-11.6,-2.06) 3(-10.8,-2.06) 5(-10,-2.06) 7(-9.2,-2.06) 9(-8.4,-2.06) 11(-7.6,-2.06) 13(-6.8,-2.06) 15(-6,-2.06) 17(-5.2,-2.06) 19(-4.4,-2.06) 21(-3.6,-2.06) 23(-2.8,-2.06) 25(-2,-2.06) 27(-1.2,-2.06) 29(-0.4,-2.06) 31(0.4,-2.06) 33(1.2,-2.06) 35(2,-2.06) 37(2.8,-2.06) 39(3.6,-2.06) 41(4.4,-2.06) 43(5.2,-2.06) 45(6,-2.06) 47(6.8,-2.06) 49(7.6,-2.06) 51(8.4,-2.06) 53(9.2,-2.06) 55(10,-2.06) 57(10.8,-2.06) 59(11.6,-2.06)
  rrect20% 0.5x1.48 smd far side paste-1: 2(-11.6,-2.06) 4(-10.8,-2.06) 6(-10,-2.06) 8(-9.2,-2.06) 10(-8.4,-2.06) 12(-7.6,-2.06) 14(-6.8,-2.06) 16(-6,-2.06) 18(-5.2,-2.06) 20(-4.4,-2.06) 22(-3.6,-2.06) 24(-2.8,-2.06) 26(-2,-2.06) 28(-1.2,-2.06) 30(-0.4,-2.06) 32(0.4,-2.06) 34(1.2,-2.06) 36(2,-2.06) 38(2.8,-2.06) 40(3.6,-2.06) 42(4.4,-2.06) 44(5.2,-2.06) 46(6,-2.06) 48(6.8,-2.06) 50(7.6,-2.06) 52(8.4,-2.06) 54(9.2,-2.06) 56(10,-2.06) 58(10.8,-2.06) 60(11.6,-2.06)
  rrect7% 1.5x2 smd: MP1(-16.5,-2.2) MP3(16.5,-2.2)
  rrect7% 1.5x2 smd far side: MP2(-16.5,-2.2) MP4(16.5,-2.2)
  silkscreen extent -18.5,-5.2 18,-0.17
Samtec_ERM8-030-01-L-D-EM2 [mm] "Receptacle, 0.8mm, 30x2, Edge mount"
  rect 1.45x0.5 smd: 1(2.075,11.6) 3(2.075,10.8) 5(2.075,10) 7(2.075,9.2) 9(2.075,8.4) 11(2.075,7.6) 13(2.075,6.8) 15(2.075,6) 17(2.075,5.2) 19(2.075,4.4) 21(2.075,3.6) 23(2.075,2.8) 25(2.075,2) 27(2.075,1.2) 29(2.075,0.4) 31(2.075,-0.4) 33(2.075,-1.2) 35(2.075,-2) 37(2.075,-2.8) 39(2.075,-3.6) 41(2.075,-4.4) 43(2.075,-5.2) 45(2.075,-6) 47(2.075,-6.8) 49(2.075,-7.6) 51(2.075,-8.4) 53(2.075,-9.2) 55(2.075,-10) 57(2.075,-10.8) 59(2.075,-11.6)
  rect 1.45x0.5 smd far side: 2(2.075,11.6) 4(2.075,10.8) 6(2.075,10) 8(2.075,9.2) 10(2.075,8.4) 12(2.075,7.6) 14(2.075,6.8) 16(2.075,6) 18(2.075,5.2) 20(2.075,4.4) 22(2.075,3.6) 24(2.075,2.8) 26(2.075,2) 28(2.075,1.2) 30(2.075,0.4) 32(2.075,-0.4) 34(2.075,-1.2) 36(2.075,-2) 38(2.075,-2.8) 40(2.075,-3.6) 42(2.075,-4.4) 44(2.075,-5.2) 46(2.075,-6) 48(2.075,-6.8) 50(2.075,-7.6) 52(2.075,-8.4) 54(2.075,-9.2) 56(2.075,-10) 58(2.075,-10.8) 60(2.075,-11.6)
  rect 2x1 smd: MP1(2.3,15) MP3(2.3,-15)
  rect 2x1 smd far side: MP2(2.3,15) MP4(2.3,-15)
  silkscreen extent 0.2,-16.5 5.2,16.5
SMA [mm] "Molded Diode, 2-Leads, Body 4.3x2.6mm, IPC Medium Density, based on OnSemi component dimensions and land pattern"
  rect 2x2 smd: 1(-2,0) 2(2,0)
  silkscreen extent -3.66,-1.57 2.79,1.57
SOT-23 [mm] "SOT23, 3-Leads, Body 2.9x1.3mm, Pitch 0.95mm, Lead Span 2.5mm, IPC Medium Density"
  rrect50% 1x0.6 smd: 1(-1.2,0.95) 2(-1.2,-0.95) 3(1.2,0)
  silkscreen extent -1.62,-1.5 0.7,1.5
SRP5030T [mm] "Bourns"
  rect 2x1.8 smd: 1(-2.25,0) 2(2.25,0)
  silkscreen extent -3.1,-2.8 3.1,2.8
SW_218-4LPST [mil] "CTS Components"
  rect 50x30 smd: 1(-150,75) 2(-150,25) 3(-150,-25) 4(-150,-75) 5(150,-75) 6(150,-25) 7(150,25) 8(150,75)
  silkscreen extent -114,-123 114,123
TEC_1-406541-1 [mm] "TE Connectivity"
  round 1.4 hole 0.89: 1(3.56,-0.18) 2(2.54,1.6) 3(1.52,-0.18) 4(0.5,1.6) 5(-0.52,-0.18) 6(-1.54,1.6) 7(-2.56,-0.18) 8(-3.58,1.6)
  round 2.1 hole 1.57: 9(8.12,0.71) 10(-8.14,0.71)
  round 3.759 hole 3.251: 11(6.34,-2.72) 12(-6.36,-2.72)
  silkscreen extent -9.69,-8 9.69,8.06
TI_Stacked_Overlay_Small [mil]
TP_H045P075 [mm] "TP_H0.45P0.75"
  round 0.75 hole 0.45: 1(0,0)
TSW-102-07-G-D [mm] "Samtec 100mil, 2x2, 230 mil above insulator"
  rrect6% 1.65x1.65 hole 1.016: 1(-1.27,-1.27)
  round 1.65 hole 1.016: 2(-1.27,1.27) 3(1.27,-1.27) 4(1.27,1.27)
  silkscreen extent -2.54,-3.5 2.54,2.54
TSW-102-07-G-S [mm] "Samtec 100mil, 1x2, 230 mil above insulator"
  rrect50% 1.65x1.65 hole 1.016: 1(-1.27,0)
  round 1.65 hole 1.016: 2(1.27,0)
  silkscreen extent -3.17,-1.27 2.54,1.27
TSW-103-07-G-D [mm] "Samtec 100mil, 2x3, 230 mil above insulator"
  rect 1.65x1.65 hole 1.016: 1(-2.54,-1.27)
  round 1.65 hole 1.016: 2(-2.54,1.27) 3(0,-1.27) 4(0,1.27) 5(2.54,-1.27) 6(2.54,1.27)
  silkscreen extent -4.83,-2.54 3.81,2.54
TSW-103-07-G-S [mm] "Samtec 100mil, 1x3, 230 mil above insulator"
  rrect50% 1.65x1.65 hole 1.016: 1(-2.54,0)
  round 1.65 hole 1.016: 2(0,0) 3(2.54,0)
TSW-104-07-G-D [mm] "Samtec 100mil, 2x4, 230 mil above insulator"
  rrect6% 1.65x1.65 hole 1.016: 1(-3.81,-1.27)
  round 1.65 hole 1.016: 2(-3.81,1.27) 3(-1.27,-1.27) 4(-1.27,1.27) 5(1.27,-1.27) 6(1.27,1.27) 7(3.81,-1.27) 8(3.81,1.27)
  silkscreen extent -6.11,-2.54 5.08,2.54
TSW-118-07-G-D [mm] "Samtec 100mil, 2x18, 230 mil above insulator"
  rrect6% 1.65x1.65 hole 1.016: 1(-21.59,-1.27)
  round 1.65 hole 1.016: 2(-21.59,1.27) 3(-19.05,-1.27) 4(-19.05,1.27) 5(-16.51,-1.27) 6(-16.51,1.27) 7(-13.97,-1.27) 8(-13.97,1.27) 9(-11.43,-1.27) 10(-11.43,1.27) 11(-8.89,-1.27) 12(-8.89,1.27) 13(-6.35,-1.27) 14(-6.35,1.27) 15(-3.81,-1.27) 16(-3.81,1.27) 17(-1.27,-1.27) 18(-1.27,1.27) 19(1.27,-1.27) 20(1.27,1.27) 21(3.81,-1.27) 22(3.81,1.27) 23(6.35,-1.27) 24(6.35,1.27) 25(8.89,-1.27) 26(8.89,1.27) 27(11.43,-1.27) 28(11.43,1.27) 29(13.97,-1.27) 30(13.97,1.27) 31(16.51,-1.27) 32(16.51,1.27) 33(19.05,-1.27) 34(19.05,1.27) 35(21.59,-1.27) 36(21.59,1.27)
  silkscreen extent -23.88,-2.54 22.86,2.54
WEEE_Minimum [mil] "WEEElie bin"
  silkscreen extent 22,-71 54,74
WL-SMCD-0603 [mm] "SMD, 2-Leads, Body 1.6x0.8mm"
  rrect13% 0.8x0.75 smd: 1(-0.8,0) 2(0.8,0)
WL-SMCW_RED [mm] "WURTH"
  rect 0.8x0.8 smd: 1(-0.8,0) 2(0.8,0)
  silkscreen extent -1.9,-0.8 1.2,0.8
XTAL_ABM3 [mm] "Abracon recommended land pattern 12.28.10"
  rect 1.9x2.4 smd: 1(-2.05,0) 2(2.05,0)
  silkscreen extent -2.67,-1.78 2.67,1.78

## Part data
C1 C11 C12 C126 C129: library part CMP-0085850-1, "CAP, CERM, 0.1 µF, 16 V,+/- 10%, X7R, 0402"
C2 C3: library part CMP-0006213-2, "CAP, CERM, 33 pF, 25 V, +/- 5%, C0G/NP0, 0402"
C4 C5 C15 C16: library part CMP-0083839-1, "CAP, CERM, 36 pF, 50 V,+/- 5%, C0G/NP0, 0402"
C6 C9: library part CMP-0860899-1, "CAP, CERM, 0.22 µF, 50 V,+/- 10%, X5R, 0603"
C7: library part CMP-0007096-4, "CAP, CERM, 0.47 uF, 50 V, +/- 10%, X7R, AEC-Q200 Grade 1, 0603"
C8 C25: library part CMP-0006412-2, "CAP, CERM, 1000 pF, 50 V, +/- 5%, C0G/NP0, 0402"
C10 C21: library part CMP-0011855-2, "CAP, TA, 10 uF, 35 V, +/- 10%, 0.125 ohm, SMD"
C13 C14 C56: library part CMP-0006356-2, "CAP, CERM, 0.1 uF, 50 V, +/- 10%, X7R, AEC-Q200 Grade 1, 0402"
C17 C20: library part CMP-0006905-4, "CAP, CERM, 0.22 uF, 16 V, +80/-20%, Y5V, 0603"
C18: library part CMP-0007138-4, "CAP, CERM, 0.47 uF, 16 V, +/- 10%, X7R, AEC-Q200 Grade 1, 0603"
C19: library part CMP-0007022-5, "CAP, CERM, 4.7 uF, 35 V, +/- 10%, X5R, 0603"
C22 C23 C24 C117: library part CMP-0078241-1, "CAP, CERM, 0.1 µF, 10 V,+/- 10%, X7R, 0402"
C26 C28 C29 C30 C31 C32 C33 C34 C35 C36 C37 C38 C39 C40 C41 C42 C43 C44 C45: "CAP, CERM, 0.1 uF, 10 V, +/- 10%, X5R, 0402"
C27: library part CMP-0006272-2, "CAP, CERM, 1 uF, 16 V, +/- 10%, X5R, 0402"
C46: "CAP, CERM, 0.01 uF, 50 V, +/- 10%, X7R, 0402"
C47: library part CMP-0079541-1, "CAP, CERM, 47 µF, 4 V,+/- 20%, X6S, 0805"
C48 C49 C94: "CAP, CERM, 27 pF, 50 V, +/- 1%, C0G/NP0, 0603"
C50 C52 C68 C70 C78 C80: "CAP, CERM, 10 uF, 25 V, +/- 20%, X7R, AEC-Q200 Grade 1, 1210"
C51: library part CMP-0006467-2, "CAP, CERM, 47 pF, 50 V, +/- 1%, C0G/NP0, 0402"
C53 C71 C81: library part CMP-0008135-2, "CAP, CERM, 1 µF, 16 V, +/- 10%, X5R, 0805"
C54 C58 C61 C69 C72 C79 C88: "CAP, CERM, 0.01 uF, 50 V, +/- 5%, X7R, 0603"
C55 C73 C83: "CAP, CERM, 0.01 uF, 50 V, +/- 10%, X7R, AEC-Q200 Grade 1, 0402"
C57: library part CMP-0011752-2, "CAP, TA, 220 µF, 6.3 V, +/- 10%, 0.7 ohm, SMD"
C59: "CAP, CERM, 100 pF, 50 V, +/- 5%, C0G/NP0, 0402"
C60 C85 C86: library part CMP-0008706-2, "CAP, CERM, 10 µF, 35 V, +/- 20%, X7R, 1206_190"
C62: library part CMP-0007067-4, "CAP, CERM, 1 uF, 35 V, +/- 10%, X7R, AEC-Q200 Grade 1, 0603"
C63: library part CMP-0011279-3, "CAP, AL, 100 uF, 50 V, +/- 20%, SMD"
C64 C66: library part CMP-0009162-2, "CAP, CERM, 4.7 uF, 50 V, +/- 10%, X7R, AEC-Q200 Grade 1, 1210"
C65 C67: library part CMP-0007094-5, "CAP, CERM, 0.22 uF, 50 V, +/- 10%, X7R, AEC-Q200 Grade 1, 0603"
C74 C75 C76 C77 C84: "CAP, CERM, 22 uF, 16 V, +/- 20%, X7R, AEC-Q200 Grade 1, 1210"
C82: library part CMP-0006236-2, "CAP, CERM, 0.01 µF, 50 V, +/- 5%, X7R, 0402"
C87: library part CMP-0007110-5, "CAP, CERM, 0.1 uF, 16 V, +/- 10%, X7R, 0603"
C91: "CAP, TA, 100 uF, 10 V, +/- 20%, 0.1 ohm, SMD"
C92: library part CMP-0007676-2, "CAP, CERM, 1 µF, 16 V, +/- 10%, X5R, 0805"
C93: library part CMP-0007960-1, "CAP, CERM, 4.7 µF, 10 V, +80/-20%, Y5V, 0805"
C95 C97 C99 C101 C103 C104 C106 C107: library part CMP-0006574-2, "CAP, CERM, 0.033 uF, 10 V, +/- 10%, X5R, 0402"
C108 C109: "CAP, CERM, 4700 pF, 2000 V, +/- 10%, X7R, 1812"
C110: library part CMP-0006620-2, "CAP, CERM, 1 uF, 35 V, +/- 20%, X5R, 0402"
C111 C114: library part CMP-0007355-6, "CAP, CERM, 10 uF, 35 V, +/- 20%, X5R, 0603"
C112 C113: library part CMP-0006526-2, "CAP, CERM, 2.2 uF, 16 V, +/- 10%, X6S, 0402"
C115: library part CMP-0006743-4, "CAP, CERM, 470 pF, 100 V, +/- 5%, X7R, 0603"
C116: library part CMP-0011708-2, "CAP, TA, 4.7 uF, 35 V, +/- 10%, 1.3 ohm, SMD"
C118 C119 C120 C121 C124 C125: library part CMP-0860896-1, "CAP, CERM, 22 pF, 50 V,+/- 5%, C0G/NP0, 0402"
C122 C123 C127 C128: library part CMP-0079539-1, "CAP, CERM, 10 pF, 16 V,+/- 10%, C0G, 0402"
D1: library part CMP-0002947-3, "LED, Red, SMD"
D2: library part CMP-0081648-2, "LED, Green, SMD"
D3 D4: library part CMP-0002934-2, "LED, Rg, SMD"
D5 D6 D7 D8 LD1 LD2 LD3 LD4 LD5 LD6: "LED, Green, SMD"
D9: library part CMP-0028762-2, "Diode, Schottky, 60 V, 1 A, AEC-Q101, SMA"
F1: library part CMP-0003588-3, "Fuse, 3 A, 32 VDC, SMD"
FID1 FID2 FID3 FID4 FID5 FID6 FID7 FID8 FID9 FID10 FID11 FID12 FID13 FID14 FID15 FID16 FID17 FID18: "Fiducial mark.  There is nothing to buy or mount."
H1 H2 H3 H4 H5 H6 H7 H8: library part CMP-0003610-1, "Standoff, Hex, 0.5\"L #4-40 Nylon"
J1 J19 J22: library part CMP-0055720-1, "Receptacle, 0.8mm, 30x2, Gold, Edge Mount"
J2: library part CMP-0075431-1, "Header, 100mil, 18x2, Gold, TH"
J3 J9: library part CMP-0075404-1, "Header, 100mil, 2x2, Gold, TH"
J4: library part CMP-0055619-1, "Receptacle, 0.8mm, 30x2, Tin, Edge mount"
J5 J6 J10 J12 J14 J18 J20: library part CMP-0075405-3, "Header, 100mil, 2x1, Gold, TH"
J8: library part CMP-0055098-2, "Header, 2.54 mm, 6x2, Gold, TH"
J11 J13: library part CMP-0055822-3, "Connector, End launch SMA, 50 ohm, SMT"
J15 J28 J33 J38 J43: "Header, 100mil, 3x1, Gold, TH"
J16: library part CMP-0078270-1, "DC POWER JACK, R/A, TH"
J17: library part CMP-0055492-1, "Terminal Block, 6x1, 5.08mm, Th"
J21 J23 J24 J29 J30 J31 J32 J34 J35 J36 J37 J39 J40 J41: "Header, 100mil, 2x1, Gold, TH"
J27: library part CMP-0054918-1, "RJ-45, Right Angle, No LED, tab up"
J42: library part CMP-0055301-1, "Connector, Receptacle, Micro-USB Type AB, R/A, Bottom Mount SMT"
L1: library part CMP-0056947-1, "Inductor, Shielded, Ferrite, 10 uH, 2.75 A, 0.128 ohm, SMD"
LD7: library part CMP-0002917-2, "LED, Green, SMD"
Logo1: library part CMP-0074844-1
Logo2: library part CMP-0074838-1, "Texas Instrument Corporate Signature"
Logo3: library part CMP-0074847-1, "FCC_disclaimer"
Logo4: library part CMP-0074769-1
M1 M2 M3 M4 M5 M6 M7 M8: library part CMP-0003617-1, "Machine Screw, Round, #4-40 x 1/4, Nylon, Philips panhead"
P1: "Header, 100mil, 4x2, Gold, TH"
P2: library part CMP-0075406-2, "Header, 100mil, 3x2, Gold, TH"
Q1 Q2 Q3 Q4: library part CMP-0064871-1, "Transistor, NPN, 60 V, 1 A, AEC-Q101, SOT-23"
R1 R2 R79 R147 R149 R157 R161 R166 R170 R175: library part CMP-0026934-3, "RES, 470, 5%, 0.063 W, AEC-Q200 Grade 0, 0402"
R3: library part CMP-0026881-2, "RES, 240 k, 5%, 0.063 W, AEC-Q200 Grade 0, 0402"
R4 R6: library part CMP-0026877-2, "RES, 220 k, 5%, 0.063 W, AEC-Q200 Grade 0, 0402"
R5: library part CMP-0026840-2, "RES, 150 k, 5%, 0.063 W, AEC-Q200 Grade 0, 0402"
R7 R9 R10: library part CMP-0027004-2, "RES, 0, 5%, 0.063 W, 0402"
R8 R75 R198: library part CMP-0026935-3, "RES, 47 k, 5%, 0.063 W, AEC-Q200 Grade 0, 0402"
R11 R12 R13 R14 R15 R16 R17 R18 R19 R20 R23 R25 R27 R29 R31 R32 R33 R34 R39 R42 R43 R44 R45 R46 R54 R55 R56 R57 R112 R113 R115 R116 R118 R119 R120 R121 R122 R124 R125 R126 R127 R128 R129 R130 R131 R132 R133 R134 R135 R136 R137 R138 R139 R140 R141 R142 R143 R144 R201 R202 R203 R204 R205 R206 R207: library part CMP-0026992-3, "RES, 0, 5%, 0.1 W, AEC-Q200 Grade 0, 0402"
R21 R22 R24 R26 R77 R78 R82 R84 R97 R99: "RES, 0, 5%, 0.1 W, 0603"
R28: library part CMP-0022891-5, "RES, 1.87 k, 1%, 0.1 W, 0603"
R30: library part CMP-0082533-1, "RES, 4.99 k, 1%, 0.1 W, 0603"
R35 R37: library part CMP-0026317-2, "RES, 374 k, 1%, 0.063 W, AEC-Q200 Grade 0, 0402"
R36 R38: library part CMP-0026660-1, "RES, 1.00 M, 1%, 0.1 W, 0402"
R40 R41: library part CMP-0025750-4, "RES, 200 k, 5%, 0.1 W, AEC-Q200 Grade 0, 0603"
R47 R48 R51 R62 R63 R64 R65 R66 R67: library part CMP-0026231-2, "RES, 2.20 k, 1%, 0.063 W, AEC-Q200 Grade 0, 0402"
R49 R50 R52 R53 R58 R59 R60 R61 R179: library part CMP-0026825-5, "RES, 10 k, 5%, 0.063 W, AEC-Q200 Grade 0, 0402"
R68 R76: library part CMP-0026822-3, "RES, 0, 5%, 0.063 W, AEC-Q200 Grade 0, 0402"
R69 R70 R71 R72: library part CMP-0027127-1, "RES, 470, 5%, 0.05 W, 0201"
R73 R197: library part CMP-0026085-3, "RES, 1.40 k, 1%, 0.063 W, AEC-Q200 Grade 0, 0402"
R74 R200: library part CMP-0026100-2, "RES, 1.00 M, 1%, 0.063 W, AEC-Q200 Grade 0, 0402"
R80: library part CMP-0026993-2, "RES, 100, 5%, 0.1 W, AEC-Q200 Grade 0, 0402"
R81 R145 R146: "RES, 1.00 M, 1%, 0.063 W, 0402"
R83: library part CMP-0026754-1, "RES, 10.0 k, 1%, 0.063 W, AEC-Q200 Grade 0, 0402"
R85 R86 R87 R88 R89: "RES, 2.2 k, 5%, 0.063 W, AEC-Q200 Grade 0, 0402"
R90: "RES, 6.04 k, 1%, 0.1 W, 0603"
R91: "RES, 6.04 k, 1%, 0.1 W, AEC-Q200 Grade 0, 0603"
R92: library part CMP-0022874-5, "RES, 1.20 k, 1%, 0.1 W, 0603"
R93: library part CMP-0021990-4, "RES, 100 k, 1%, 0.1 W, AEC-Q200 Grade 0, 0603"
R94 R98 R101: "RES, 2.40 k, 0.1%, 0.1 W, AEC-Q200 Grade 0, 0603"
R95: library part CMP-0022237-4, "RES, 24.9 k, 1%, 0.1 W, AEC-Q200 Grade 0, 0603"
R96: library part CMP-0022992-5, "RES, 2.55 k, 1%, 0.1 W, 0603"
R100: "RES, 4.22 k, 1%, 0.1 W, AEC-Q200 Grade 0, 0603"
R102 R103 R104 R105: "RES, 470, 5%, 0.063 W, AEC-Q200 Grade 0, 0402"
R106: "RES, 10.0 k, 1%, 0.1 W, 0603"
R107 R114 R117 R123: "RES, 75.0, 1%, 0.063 W, AEC-Q200 Grade 0, 0402"
R108 R109 R110 R111 R148 R150 R151 R153 R154 R156 R158 R159 R160 R162 R163 R164 R165 R167 R168 R169 R171 R172 R173: library part CMP-0026237-2, "RES, 2.49 k, 1%, 0.063 W, AEC-Q200 Grade 0, 0402"
R152 R155: library part CMP-0026512-2, "RES, 6.04 k, 1%, 0.063 W, AEC-Q200 Grade 0, 0402"
R174: library part CMP-0026768-2, "RES, 100 k, 0.5%, 0.063 W, AEC-Q200 Grade 0, 0402"
R176: library part CMP-0026036-3, "RES, 165 k, 1%, 0.063 W, AEC-Q200 Grade 0, 0402"
R177: library part CMP-0026908-3, "RES, 33, 5%, 0.063 W, AEC-Q200 Grade 0, 0402"
R178: library part CMP-0026088-3, "RES, 1.50 k, 1%, 0.063 W, AEC-Q200 Grade 0, 0402"
R180 R183 R196 R199: library part CMP-0026888-3, "RES, 27, 5%, 0.063 W, AEC-Q200 Grade 0, 0402"
R181 R182 R184 R185 R192 R193: library part CMP-0026880-3, "RES, 22, 5%, 0.063 W, AEC-Q200 Grade 0, 0402"
R186 R187 R188 R189 R190 R191 R194 R195: library part CMP-0026027-3, "RES, 15.0 k, 1%, 0.063 W, AEC-Q200 Grade 0, 0402"
S1: library part CMP-0002128-2, "Switch, Slide, SPST 4 poles, SMT"
S2 S3: library part CMP-0002170-2, "Switch, Normally open, 2.3N force, 200k operations, SMD"
SH-J1 SH-J2 SH-J3 SH-J4 SH-J5 SH-J6 SH-J7 SH-J8: library part CMP-0078738-1, "Single Operation 2.54mm Pitch Open Top Jumper Socket"
T1: library part CMP-0090858-1, "350µH LAN 10/100/1000 Base-T Pulse Transformer 1:1 Surface Mount"
TP1 TP2 TP3 TP4 TP5 TP6 TP7 TP8 TP9 TP10 VPP_TP1: library part CMP-0003719-1, "Testpoint"
U1: library part CMP-0039268-4, "16-Bit Ultra-Low-Power Microcontroller, 128KB Flash, 8KB RAM, USB, 12Bit ADC, 2 USCIs, 32Bit HW MPY, RGC0064B (VQFN-64)"
U2 U3: library part CMP-0066434-1, "Dual Bidirectional Multi-Voltage Level Translator, DQE0008A (X2SON-8)"
U4: library part CMP-0038965-1, "25 MHz Mixed Signal Microcontroller with 128 KB Flash, 8192 B SRAM and 63 GPIOs, -40 to 85 degC, 80-pin QFP (PN), Green (RoHS & no Sb/Br)"
U5: library part CMP-0090870-2, "Hi-Reliability, High Immunity, Radiation Resistant, Gigabit Ethernet PHY"
U6: library part CMP-0081171-4, "3.8-V to 36-V 2-A Synchronous Step-Down Voltage Regulator, RNX0012B (VQFN-HR-12)"
U7 U8 U9: library part CMP-0036893-1, "Single Output Fast Transient Response LDO, 1.5 A, Adjustable 1.21 to 20 V Output, 2.1 to 20 V Input, 5-pin DDPAK (KTT), -40 to 125 degC, Green (RoHS & no Sb/Br)"
U10: library part CMP-0036362-5, "Single Output LDO, 500mA, Adj. (0.8 to 3.6V), Programmable Soft-Start, DRC0010J (VSON-10)"
U11 U12: "4-Channel Ultra-Low-Capacitance IEC ESD Protection Diode, DQA0010A (USON-10)"
U13: library part CMP-0036447-1, "Single Output Low Noise LDO, 500 mA, Adjustable 1.3 to 6.5 V Output, 2.5 to 16 V Input, 8-pin SOIC (D), -40 to 125 degC, Green (RoHS & no Sb/Br)"
U14: library part CMP-0033743-2, "4-Port Full-Speed USB Hub, 3.3V, -40 to 85 degC, 32-Pin QFN (RHB), Green (RoHS & no Sb/Br)"
XTAL1: "Crystal, 25 MHz, 18 pF, SMD"
Y1: library part CMP-0085483-1, "Oscillator, 4 MHz, 700 ppm, 39 pF, SMD"
Y2: library part CMP-0004637-3, "Crystal, 24 MHz, 20pF, SMD"
Y3: library part CMP-0006147-4, "Resonator, 6 MHz, 15pF SMD"
ZZ1: library part CMP-0077236-1
ZZ2: library part CMP-0077237-1
ZZ3: library part CMP-0077238-1

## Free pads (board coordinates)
  round 126 hole 106: 2(6273.99,570.39) 2(6273.99,2269.85) 2(6583.67,99.76) 2(6583.67,1799.21) 2(6626.81,2268.37) 2(6626.81,2515.11) 2(7266.97,2268.37) 2(7266.97,2515.11) 2(7355.61,100) 2(7355.61,1799.46) 2(7706.65,2268.68) 2(7706.65,2515.42) 2(8346.81,2268.68) 2(8346.81,2515.42) 2(8436.12,100.39) 2(8436.12,1799.85)
  round 0 hole 10 unplated mask+0: 3(6397.55,452.8) 3(6397.55,477.17) 3(6397.55,501.54) 3(6397.55,1346.69) 3(6397.55,1371.06) 3(6397.55,1395.43) 3(6462.29,452.8) 3(6462.29,477.17) 3(6462.29,501.54) 3(6462.29,1346.69) 3(6462.29,1371.06) 3(6462.29,1395.43) 3(6886.81,2112.61) 3(6886.81,2176.35) 3(6886.81,2359.35) 3(6886.81,2423.09) 3(6911.18,2112.61) 3(6911.18,2176.35) 3(6911.18,2359.35) 3(6911.18,2423.09) 3(6935.55,2112.61) 3(6935.55,2176.35) 3(6935.55,2359.35) 3(6935.55,2423.09) 3(7477.68,453.1) 3(7477.68,477.47) 3(7477.68,501.84) 3(7477.68,1347) 3(7477.68,1371.37) 3(7477.68,1395.74) 3(7542.42,453.1) 3(7542.42,477.47) 3(7542.42,501.84) 3(7542.42,1347) 3(7542.42,1371.37) 3(7542.42,1395.74) 3(7966.65,2112.91) 3(7966.65,2176.65) 3(7966.65,2359.65) 3(7966.65,2423.39) 3(7991.02,2112.91) 3(7991.02,2176.65) 3(7991.02,2359.65) 3(7991.02,2423.39) 3(8015.39,2112.91) 3(8015.39,2176.65) 3(8015.39,2359.65) 3(8015.39,2423.39)

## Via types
v1: diameter 24, hole 12, Top Layer to Bottom Layer, tented both sides, 905 vias
v2: diameter 24, hole 12, Top Layer to Bottom Layer, 63 vias
v3: diameter 18, hole 7.87, Top Layer to Bottom Layer, tented both sides, 53 vias
v4: diameter 22, hole 10, Top Layer to Bottom Layer, tented both sides, 43 vias
v5: diameter 19.68, hole 7.87, Top Layer to Bottom Layer, 21 vias
v6: diameter 22, hole 12, Top Layer to Bottom Layer, tented both sides, 1 vias

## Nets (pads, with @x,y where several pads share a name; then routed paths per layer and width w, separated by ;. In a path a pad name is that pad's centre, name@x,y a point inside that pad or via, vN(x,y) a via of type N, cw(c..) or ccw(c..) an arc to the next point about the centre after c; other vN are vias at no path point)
1V1: C86.1 C87.1 C88.2 J24.1 R28.2 R106.1 R111.1 U10.9 U10.10 | length 67.2
  Top Layer w9: U10.9@690.12,3418.39 685.5,3418.39 681.85,3422.04 697.34,3422.04 U10.9@698,3422.7
  Bottom Layer w20: v1(1233.79,3543.61) 1274.22,3543.61 R111.1@1274.6,3543.23
  other v1: 886,3379.7 937,3380.7 940,3434.7 889.81,3441.28
1V8: C52.1 C53.1 C55.1 J23.1 P2.1 R92.2 R110.1 U7.4 | length 219.4
  Top Layer w40: U7.4@788.42,5114.63 900.93,5114.63 930.31,5144.01 993.35,5144.01 C52.1@995,5145.66
  other v1: 1134.81,5130.28 1193.81,5132.28 1263.31,5134.7 1211,5199.7 1269,5199.7 967,5200.7 1037,5200.7 1097,5200.7 1155,5200.7
2V5: C70.1 C71.1 C73.1 J20.1 P2.3 R96.2 R109.1 U8.4 | length 688.4
  Top Layer w60: 1650,4556.7 1558,4464.7 1558,4026.7 1593,3991.7 P2.3@1663.83,3991.7
  other v1: 1096.81,4581.28 1169.21,4588.37 1227.81,4608.28 993,4664.7 1059,4664.7 1126,4664.7 1194,4664.7 1262,4664.7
